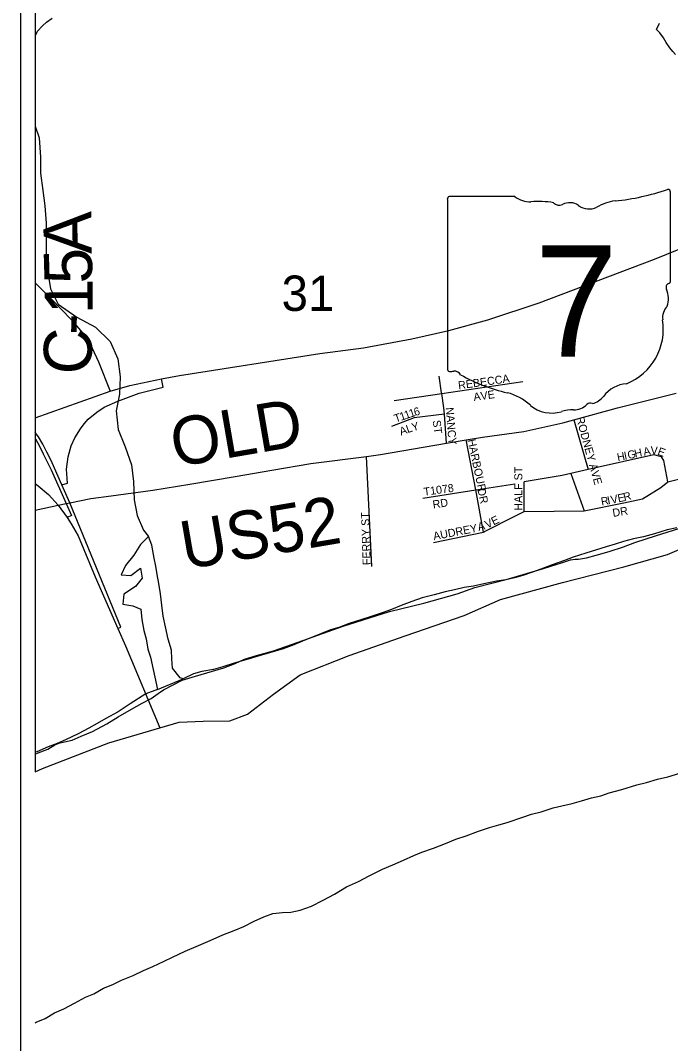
# Model space of a CAD drawing. Extents: x 0 to 34, y 0 to 22.
# Drawn here: x 2.6 to 3.368, y 14.848 to 16.058 of the extents above; entities that cross this region are included whole.
import ezdxf

# ---------------------------------------------------------------- set-up
doc = ezdxf.new("R2010")
doc.units = 0
for name, color, linetype in [('GM_X_County', 7, 'Continuous'), ('GM_X_County_Road', 7, 'Continuous'), ('GM_X_County_Road_Text', 7, 'Continuous'), ('GM_X_Interchange_Ramps', 7, 'Continuous'), ('GM_X_Major_River', 7, 'Continuous'), ('GM_X_Minor_River', 7, 'Continuous'), ('GM_X_Section', 7, 'Continuous'), ('GM_X_Section_Text', 7, 'Continuous'), ('GM_X_State_Location', 7, 'Continuous'), ('GM_X_State_Route', 7, 'Continuous'), ('GM_X_State_Shield', 7, 'Continuous'), ('GM_X_Township', 7, 'Continuous'), ('GM_X_Township_Subdivision', 7, 'Continuous'), ('GM_X_Township_Subdivision_Text', 7, 'Continuous'), ('GM_X_US_Route', 7, 'Continuous'), ('SH_Data', 7, 'Continuous')]:
    doc.layers.add(name, color=color, linetype=linetype)

msp = doc.modelspace()

# ---------------------------------------------------------------- linework, layer by layer
at = {"layer": 'GM_X_County'}
for points in [[(9.4175, 16.6203), (9.4175, 20.9), (2.6175, 20.9), (2.6175, 15.1694)], [(2.6175, 15.1694), (2.626, 15.1733), (2.7045, 15.2038), (2.7647, 15.2216), (2.7876, 15.2283), (2.816, 15.2295), (2.8475, 15.2299), (2.8684, 15.2379), (2.899, 15.2615), (2.9305, 15.2843), (2.9885, 15.3072), (3.0549, 15.3305), (3.1246, 15.3545), (3.1675, 15.3732), (3.2407, 15.3935), (3.3131, 15.4122), (3.3647, 15.4264), (3.3973, 15.4405)]]:
    msp.add_lwpolyline(points, dxfattribs=at)
at = {"layer": 'GM_X_County_Road'}
for points in [[(2.6175, 15.7478), (2.6371, 15.7282), (2.6597, 15.7051), (2.6734, 15.689), (2.6847, 15.6706), (2.6923, 15.6546), (2.7062, 15.6198)], [(2.6175, 15.4792), (2.6447, 15.4851), (2.6539, 15.487), (2.6583, 15.4878), (2.6831, 15.4928), (2.7073, 15.4958), (2.7563, 15.5027), (2.8002, 15.5098), (2.8537, 15.5187), (2.8972, 15.5264), (2.9431, 15.5341), (3.0089, 15.5427), (3.0257, 15.5449), (3.1035, 15.5581), (3.127, 15.5621), (3.1462, 15.5653), (3.195, 15.5719), (3.2413, 15.5822), (3.2542, 15.5858), (3.3056, 15.6002), (3.3749, 15.6174)]]:
    msp.add_lwpolyline(points, dxfattribs=at)
at = {"layer": 'GM_X_Interchange_Ramps'}
for points in [[(2.649, 15.5091), (2.6554, 15.511), (2.6544, 15.5276), (2.6565, 15.5421), (2.66, 15.5553), (2.6643, 15.5647), (2.6708, 15.5752), (2.6751, 15.5812), (2.6801, 15.5868), (2.6902, 15.595), (2.699, 15.6008), (2.7152, 15.6079), (2.7404, 15.6174), (2.7686, 15.6246), (2.7667, 15.6343)], [(2.715, 15.3389), (2.7188, 15.3405), (2.6583, 15.4878), (2.649, 15.5091), (2.6404, 15.5286), (2.6361, 15.5376), (2.6312, 15.5478), (2.6265, 15.557), (2.6215, 15.5659), (2.6175, 15.5711)], [(2.6175, 15.5635), (2.6176, 15.5633), (2.6225, 15.5548), (2.627, 15.5458), (2.6319, 15.5356), (2.6361, 15.5267), (2.6539, 15.487), (2.6603, 15.4727), (2.6551, 15.4703)]]:
    msp.add_lwpolyline(points, dxfattribs=at)
at = {"layer": 'GM_X_Major_River'}
msp.add_line((2.7618, 15.2669), (2.7925, 15.2795), dxfattribs=at)
for points in [[(3.376, 15.4583), (3.3643, 15.4556), (3.3495, 15.451), (3.3363, 15.4476), (3.3246, 15.4453), (3.3128, 15.4418), (3.303, 15.4388), (3.2924, 15.4357), (3.2682, 15.428), (3.2535, 15.4234), (3.2429, 15.4196), (3.2285, 15.4143), (3.2153, 15.4093), (3.2051, 15.4055), (3.1937, 15.4016), (3.1839, 15.399), (3.1737, 15.3967), (3.1627, 15.3951), (3.1476, 15.392), (3.1355, 15.389), (3.1245, 15.3874), (3.1131, 15.3847), (3.1022, 15.3824), (3.0889, 15.379), (3.0749, 15.3755), (3.0628, 15.3709), (3.05, 15.3663), (3.0386, 15.3614), (3.0288, 15.3579), (3.0133, 15.353), (3.0023, 15.3495), (2.9887, 15.3449), (2.9762, 15.3403), (2.9664, 15.3373), (2.9558, 15.3331), (2.9441, 15.3285), (2.9335, 15.3239), (2.9233, 15.3197), (2.9105, 15.3151), (2.8942, 15.3101), (2.8821, 15.3067), (2.8692, 15.3029), (2.8526, 15.2979), (2.8394, 15.2937), (2.828, 15.2906), (2.8144, 15.2883), (2.8046, 15.2856), (2.7925, 15.2795)], [(2.7925, 15.2795), (2.7887, 15.2806), (2.7799, 15.292), (2.7788, 15.303), (2.7784, 15.3136), (2.7745, 15.3265), (2.7715, 15.3409), (2.7688, 15.3538), (2.7672, 15.3667), (2.7657, 15.38), (2.7634, 15.3921), (2.7615, 15.4031), (2.7599, 15.4126), (2.758, 15.4224), (2.7553, 15.4376), (2.7515, 15.4478), (2.7417, 15.4383), (2.7341, 15.4258), (2.724, 15.4136), (2.7191, 15.4026), (2.7304, 15.4019), (2.7418, 15.4106), (2.7437, 15.3985), (2.7358, 15.3886), (2.7222, 15.3798), (2.7211, 15.3677), (2.7328, 15.3658), (2.7423, 15.3621), (2.7434, 15.3499), (2.7457, 15.3367), (2.7484, 15.3268), (2.7507, 15.3147), (2.7538, 15.3052), (2.7618, 15.2669)], [(2.7618, 15.2669), (2.7482, 15.2619), (2.7297, 15.2498), (2.7154, 15.2406), (2.701, 15.2326), (2.6908, 15.2265), (2.681, 15.2212), (2.6681, 15.2143), (2.6534, 15.2075), (2.6432, 15.2029), (2.6326, 15.1991), (2.6193, 15.1933), (2.6175, 15.1927)], [(3.3284, 15.154), (3.3401, 15.157), (3.353, 15.1609), (3.3651, 15.1635), (3.3794, 15.1681)], [(2.6175, 14.8726), (2.6187, 14.8733), (2.6293, 14.8779), (2.6402, 14.8844), (2.6512, 14.8893), (2.664, 14.8958), (2.6769, 14.903), (2.6867, 14.9068), (2.6981, 14.9137), (2.709, 14.9179), (2.7196, 14.9229), (2.7332, 14.9286), (2.7453, 14.9343), (2.7563, 14.9393), (2.7699, 14.9454), (2.7797, 14.9503), (2.7948, 14.9572), (2.8103, 14.9641), (2.8243, 14.9698), (2.8391, 14.9766), (2.8527, 14.982), (2.864, 14.9866), (2.8761, 14.9927), (2.8875, 14.998), (2.8984, 15.0018), (2.9098, 15.003), (2.9196, 15.0034), (2.9306, 15.0057), (2.9442, 15.0107), (2.9578, 15.0175), (2.9714, 15.0248), (2.9854, 15.0335), (2.9994, 15.0397), (3.0122, 15.0465), (3.0281, 15.0545), (3.0402, 15.0595), (3.0527, 15.0652), (3.0648, 15.0706), (3.0746, 15.0744), (3.0882, 15.0793), (3.1026, 15.0847), (3.1147, 15.09), (3.1268, 15.0939), (3.1415, 15.0992), (3.1544, 15.1038), (3.1654, 15.1069), (3.1752, 15.1095), (3.1937, 15.1157), (3.2039, 15.1195), (3.2157, 15.1222), (3.2297, 15.1268), (3.2399, 15.1291), (3.252, 15.1321), (3.2633, 15.1352), (3.2751, 15.1386), (3.286, 15.1413), (3.2959, 15.1448), (3.311, 15.1486), (3.3284, 15.154)]]:
    msp.add_lwpolyline(points, dxfattribs=at)
at = {"layer": 'GM_X_Minor_River'}
for points in [[(2.6175, 16.0402), (2.6178, 16.0406), (2.6202, 16.0456), (2.626, 16.0519), (2.6306, 16.0564), (2.6375, 16.0612)], [(3.3742, 16.018), (3.3712, 16.0218), (3.3675, 16.0261), (3.3634, 16.0322), (3.3601, 16.0376), (3.3557, 16.0438), (3.352, 16.0476), (3.3555, 16.0552)], [(2.6175, 15.9331), (2.6222, 15.9195), (2.6237, 15.8967), (2.6236, 15.8777), (2.6266, 15.8572), (2.6289, 15.839), (2.6304, 15.8184), (2.6303, 15.7805), (2.6325, 15.76), (2.6355, 15.741), (2.6446, 15.7227), (2.6665, 15.7075), (2.6885, 15.6954), (2.7059, 15.6786), (2.7149, 15.6581), (2.7179, 15.6369), (2.7171, 15.6164), (2.7133, 15.5966), (2.7155, 15.5746), (2.7238, 15.5541), (2.7314, 15.5328), (2.7336, 15.5131), (2.7343, 15.4911), (2.7381, 15.4729), (2.7456, 15.4554), (2.7515, 15.4478)]]:
    msp.add_lwpolyline(points, dxfattribs=at)
at = {"layer": 'GM_X_Section'}
msp.add_line((2.6175, 16.1358), (2.6175, 15.1906), dxfattribs=at)
msp.add_lwpolyline([(2.6175, 15.1906), (2.6211, 15.1919), (2.6324, 15.1964), (2.6408, 15.2014), (2.6453, 15.2033), (2.6521, 15.2048), (2.6612, 15.2071), (2.6718, 15.2116), (2.6851, 15.2173), (2.7021, 15.2264), (2.7154, 15.2344), (2.7313, 15.2435), (2.7438, 15.2507), (2.7544, 15.2564), (2.7627, 15.2621), (2.7692, 15.2666), (2.7911, 15.278), (2.8067, 15.2826), (2.8203, 15.2868), (2.8404, 15.2925), (2.8536, 15.2978), (2.865, 15.3027), (2.879, 15.3073), (2.8991, 15.3126), (2.9283, 15.3228), (2.9813, 15.3418), (3.0362, 15.3593), (3.0768, 15.3692), (3.1162, 15.3802), (3.137, 15.3874), (3.1571, 15.3927), (3.1741, 15.3969), (3.2181, 15.4102), (3.2408, 15.417), (3.2503, 15.4204), (3.2556, 15.4212), (3.2597, 15.4212), (3.2692, 15.4227), (3.2806, 15.4258), (3.2957, 15.4303), (3.3128, 15.4356), (3.3264, 15.4406), (3.3518, 15.4489), (3.3783, 15.4573)], dxfattribs=at)
at = {"layer": 'GM_X_State_Route'}
msp.add_lwpolyline([(2.6175, 15.5883), (2.7062, 15.6198), (2.7293, 15.6264), (2.7667, 15.6343), (2.788, 15.6383), (2.9539, 15.6644), (3.0054, 15.6711), (3.0626, 15.6819), (3.1065, 15.6914), (3.1523, 15.7042), (3.2131, 15.7243), (3.3496, 15.7758), (3.4573, 15.8196), (3.5135, 15.8424), (3.5323, 15.8489), (3.5957, 15.8695), (3.654, 15.8839), (3.8199, 15.9215), (3.8392, 15.926)], dxfattribs=at)
at = {"layer": 'GM_X_State_Shield'}
for p, q in [((3.3683, 15.7504), (3.3683, 15.8551)), ((3.1046, 15.8467), (3.1046, 15.6466)), ((3.1844, 15.8501), (3.1072, 15.8501)), ((3.3683, 15.7504), (3.3683, 15.7504))]:
    msp.add_line(p, q, dxfattribs=at)
for centre, radius, start, end in [((3.2744, 16.123), 0.2796, 275.8445, 288.9065), ((3.3654, 15.8555), 0.00294, 351.8621, 97.738), ((3.1076, 15.8471), 0.00305, 98.1301, 188.1301), ((3.2028, 15.8734), 0.0296, 231.6195, 271.1119), ((3.2126, 15.7378), 0.1064, 80.4867, 94.9883), ((3.2368, 15.8482), 0.00855, 219.7921, 297.1024), ((3.2493, 15.825), 0.0178, 54.4667, 119.1411), ((3.31, 15.789), 0.0563, 97.3462, 120.7689), ((3.2723, 15.8568), 0.0214, 233.8562, 294.8282), ((3.3676, 15.7427), 0.00454, 107.944, 210.337), ((3.3652, 15.75), 0.00314, 289.6038, 7.7341), ((3.3387, 15.7295), 0.0273, 340.033, 23.6496), ((3.3788, 15.7066), 0.0198, 136.8065, 186.9296), ((3.29, 15.6933), 0.0699, 292.3089, 8.9858), ((3.1077, 15.6461), 0.00308, 171.9584, 258.3066), ((3.1081, 15.6666), 0.0235, 267.339, 280.6039), ((3.1129, 15.635), 0.00848, 29.7484, 93.2717), ((3.22, 15.8148), 0.2019, 240.4129, 257.1985), ((3.3195, 15.5904), 0.0383, 94.4031, 142.5768), ((3.1598, 15.5567), 0.0632, 47.1842, 75.836), ((3.271, 15.6272), 0.0226, 282.8732, 323.2771), ((3.2281, 15.634), 0.0401, 230.7004, 286.2918), ((3.2542, 15.6191), 0.0214, 268.777, 315.5493), ((3.2736, 15.5997), 0.00601, 65.7517, 132.6484), ((3.2513, 15.5649), 0.0329, 85.6951, 111.2099)]:
    msp.add_arc(centre, radius, start, end, dxfattribs=at)
at = {"layer": 'GM_X_Township'}
msp.add_line((2.6175, 19.3567), (2.6175, 15.1694), dxfattribs=at)
msp.add_lwpolyline([(2.6175, 15.1694), (2.626, 15.1733), (2.7045, 15.2038), (2.7647, 15.2216), (2.7876, 15.2283), (2.816, 15.2295), (2.8475, 15.2299), (2.8684, 15.2379), (2.899, 15.2615), (2.9305, 15.2843), (2.9885, 15.3072), (3.0549, 15.3305), (3.1246, 15.3545), (3.1675, 15.3732), (3.2407, 15.3935), (3.3131, 15.4122), (3.3647, 15.4264), (3.3973, 15.4405)], dxfattribs=at)
at = {"layer": 'GM_X_Township_Subdivision'}
for points in [[(3.0978, 15.6178), (3.0948, 15.6376)], [(3.0418, 15.6087), (3.098, 15.617), (3.1937, 15.6311)], [(3.1035, 15.5581), (3.1011, 15.5926), (3.1006, 15.5999), (3.098, 15.617), (3.0978, 15.6178)], [(3.1011, 15.5926), (3.0654, 15.5881), (3.0386, 15.5781)], [(3.2542, 15.5858), (3.2711, 15.5271)], [(3.1475, 15.4532), (3.1381, 15.5031), (3.127, 15.5621)], [(3.0153, 15.4125), (3.0089, 15.5427)], [(3.3654, 15.5127), (3.3604, 15.5379), (3.3578, 15.5421), (3.3486, 15.5446), (3.2711, 15.5271), (3.2507, 15.5225), (3.2405, 15.5202), (3.1953, 15.5127)], [(3.2507, 15.5225), (3.2665, 15.4783), (3.3134, 15.4876), (3.3352, 15.4926), (3.357, 15.506), (3.3654, 15.5127), (3.4132, 15.5247), (3.4428, 15.5321), (3.4727, 15.5397)], [(3.0755, 15.4934), (3.1381, 15.5031), (3.1844, 15.5102)], [(3.1953, 15.4775), (3.1953, 15.5127)], [(3.1485, 15.4537), (3.1852, 15.4724), (3.1853, 15.4724)], [(3.1853, 15.4724), (3.1953, 15.4775), (3.2665, 15.4783)], [(3.0881, 15.4406), (3.1475, 15.4532), (3.1485, 15.4536), (3.1485, 15.4537)]]:
    msp.add_lwpolyline(points, dxfattribs=at)
at = {"layer": 'GM_X_US_Route'}
for points in [[(2.6175, 15.5104), (2.621, 15.508), (2.633, 15.4977), (2.6447, 15.4851), (2.6551, 15.4703), (2.6601, 15.4628), (2.6682, 15.4486), (2.6882, 15.4), (2.715, 15.3389)], [(2.715, 15.3389), (2.724, 15.3184), (2.7647, 15.2216)]]:
    msp.add_lwpolyline(points, dxfattribs=at)
at = {"layer": 'SH_Data'}
msp.add_line((2.6, 20.9), (2.6, 14.1), dxfattribs=at)

# ---------------------------------------------------------------- texts
at = {"layer": 'GM_X_County_Road_Text'}
for s, height, rotation, p in [('A', 0.0568, 90.6521, (2.6843, 15.7822)), ('5', 0.0568, 91.672, (2.6853, 15.7475)), ('1', 0.0568, 90.3231, (2.6855, 15.711)), ('-', 0.0568, 88.6093, (2.6849, 15.6858)), ('C', 0.0568, 88.3996, (2.6836, 15.639)), ('OLD', 0.05682, 9.7823, (2.7828, 15.5297)), ('US52', 0.05682, 9.7038, (2.7943, 15.4087))]:
    msp.add_text(s, height=height, rotation=rotation, dxfattribs=at).set_placement(p)
at = {"layer": 'GM_X_Section_Text'}
msp.add_text('31', height=0.04186, rotation=0, dxfattribs=at).set_placement((2.9087, 15.7147))
at = {"layer": 'GM_X_State_Location'}
for s in ['s', 'r']:
    msp.add_text(s, height=0.000189, dxfattribs=at).set_placement((3.2335, 15.7333))
msp.add_text('7', height=0.000189, rotation=0, dxfattribs=at).set_placement((3.205, 15.7196))
at = {"layer": 'GM_X_State_Shield'}
msp.add_text('7', height=0.1318, dxfattribs=at).set_placement((3.208, 15.6607))
at = {"layer": 'GM_X_Township_Subdivision_Text'}
for s, rotation, p in [('REBECCA', 8.0044, (3.118, 15.6219)), ('AVE', 7.8534, (3.1361, 15.6082)), ('6', 15.0228, (3.0663, 15.5903)), ('NANCY', 274.7656, (3.1026, 15.6003)), ('T', 18.8307, (3.0435, 15.5826)), ('1', 18.8311, (3.0499, 15.5847)), ('1', 18.8311, (3.0554, 15.5866)), ('1', 17.9912, (3.0609, 15.5885)), ('RODNEY AVE', 285.4211, (3.2567, 15.5881)), ('A', 19.7733, (3.0499, 15.5673)), ('L', 19.2878, (3.0577, 15.5701)), ('Y', 16.3201, (3.0639, 15.5723)), ('ST', 277.1346, (3.0872, 15.585)), ('HARBOUR', 281.9761, (3.1284, 15.5621)), ('H', 11.7759, (3.3266, 15.5411)), ('A', 11.7772, (3.3372, 15.5433)), ('V', 358.6354, (3.3448, 15.545)), ('E', 339.6885, (3.3523, 15.5449)), ('H', 11.7772, (3.3062, 15.5368)), ('I', 11.7772, (3.3144, 15.5385)), ('G', 11.7772, (3.3185, 15.5394)), ('HALF ST', 90, (3.1932, 15.4784)), ('T1078', 7.9071, (3.0772, 15.496)), ('DR', 282.5222, (3.14, 15.5038)), ('RD', 8.974, (3.088, 15.4809)), ('R', 10.9986, (3.2871, 15.4844)), ('I', 11.0051, (3.2945, 15.4858)), ('V', 11.0023, (3.2986, 15.4866)), ('E', 11.9895, (3.3069, 15.4882)), ('R', 14.6615, (3.3139, 15.4897)), ('DR', 9.4608, (3.3006, 15.471)), ('FERRY ST', 91.7924, (3.014, 15.4142)), ('V', 26.0408, (3.1517, 15.4572)), ('E', 26.5623, (3.1593, 15.4609)), ('AUDREY', 10.9229, (3.0888, 15.4435)), ('A', 14.4935, (3.1417, 15.4544))]:
    msp.add_text(s, height=0.00947, rotation=rotation, dxfattribs=at).set_placement(p)

doc.saveas('drawing.dxf')
